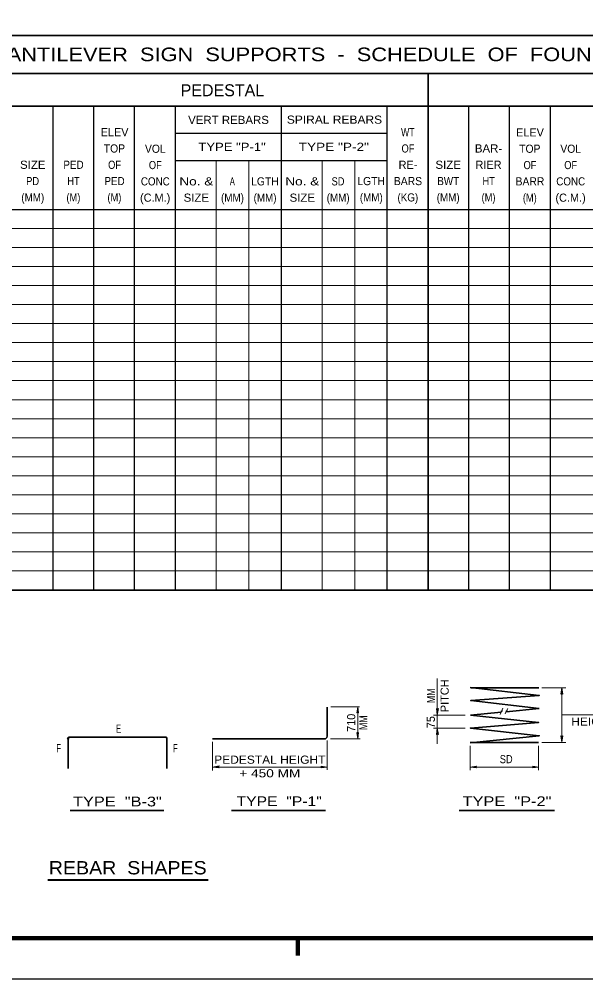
# Model space of a CAD drawing. Extents: x 312601.858 to 312602.699, y 144420.109 to 144420.704.
# Drawn here: x 312602.1757 to 312602.3843, y 144420.1095 to 144420.4624 of the extents above; entities that cross this region are included whole.
import ezdxf
from ezdxf.enums import TextEntityAlignment as Align

# ---------------------------------------------------------------- set-up
doc = ezdxf.new("R2010")
doc.units = 0
doc.header["$LTSCALE"] = 0.0012
doc.header["$PDMODE"] = 32
doc.header["$PDSIZE"] = 0.0006
for name, color, linetype, lineweight in [('1', 7, 'Continuous', 13), ('2', 7, 'Continuous', 13), ('39', 7, 'Continuous', 13)]:
    doc.layers.add(name, color=color, linetype=linetype, lineweight=lineweight)

msp = doc.modelspace()

# ---------------------------------------------------------------- hatches: boundary and pattern name
at = {"layer": '39'}
for points in [[(312602.3754, 144420.2144), (312602.3751, 144420.2142), (312602.3754, 144420.2166), (312602.3758, 144420.2142)], [(312602.3754, 144420.2144), (312602.3751, 144420.2142), (312602.3754, 144420.2166), (312602.3758, 144420.2142)], [(312602.3754, 144420.2144), (312602.3751, 144420.2142), (312602.3754, 144420.2166), (312602.3758, 144420.2142)], [(312602.3296, 144420.2087), (312602.33, 144420.2089), (312602.3296, 144420.2065), (312602.3293, 144420.2089)], [(312602.3296, 144420.1995), (312602.3293, 144420.1993), (312602.3296, 144420.2017), (312602.33, 144420.1993)], [(312602.3754, 144420.1987), (312602.3758, 144420.1989), (312602.3754, 144420.1965), (312602.3751, 144420.1989)], [(312602.3754, 144420.1987), (312602.3758, 144420.1989), (312602.3754, 144420.1965), (312602.3751, 144420.1989)], [(312602.3754, 144420.1987), (312602.3758, 144420.1989), (312602.3754, 144420.1965), (312602.3751, 144420.1989)], [(312602.2491, 144420.1874), (312602.2493, 144420.1871), (312602.2469, 144420.1874), (312602.2493, 144420.1878)], [(312602.2491, 144420.1874), (312602.2493, 144420.1871), (312602.2469, 144420.1874), (312602.2493, 144420.1878)], [(312602.2491, 144420.1874), (312602.2493, 144420.1871), (312602.2469, 144420.1874), (312602.2493, 144420.1878)]]:
    msp.add_hatch(color=256, dxfattribs=at).paths.add_polyline_path(points)

# ---------------------------------------------------------------- linework, layer by layer
at = {"layer": '1', "lineweight": 35}
for p, q in [((312602.159, 144420.4565), (312602.6412, 144420.4565)), ((312602.159, 144420.4425), (312602.6412, 144420.4425)), ((312602.3262, 144420.2525), (312602.3262, 144420.4425)), ((312602.1584, 144420.4305), (312602.6008, 144420.4305)), ((312602.1584, 144420.2525), (312602.6412, 144420.2525)), ((312602.3421, 144420.2165), (312602.367, 144420.2165)), ((312602.289, 144420.2094), (312602.289, 144420.1987)), ((312602.3418, 144420.2065), (312602.3531, 144420.2076)), ((312602.355, 144420.2077), (312602.3671, 144420.2089)), ((312602.1937, 144420.1869), (312602.1937, 144420.198)), ((312602.1941, 144420.1984), (312602.2297, 144420.1984)), ((312602.2301, 144420.198), (312602.2301, 144420.1868)), ((312602.2468, 144420.1977), (312602.288, 144420.1977)), ((312602.3417, 144420.1964), (312602.3669, 144420.1964)), ((312602.1945, 144420.1714), (312602.2289, 144420.1714)), ((312602.2539, 144420.1714), (312602.2885, 144420.1714)), ((312602.3377, 144420.1714), (312602.3727, 144420.1714))]:
    msp.add_line(p, q, dxfattribs=at)
at = {"layer": '1', "lineweight": 25}
for p, q in [((312602.1882, 144420.2525), (312602.1882, 144420.4305)), ((312602.2032, 144420.2525), (312602.2032, 144420.4305)), ((312602.2182, 144420.2525), (312602.2182, 144420.4305)), ((312602.2332, 144420.2525), (312602.2332, 144420.4305)), ((312602.2722, 144420.2525), (312602.2722, 144420.4305)), ((312602.3112, 144420.2525), (312602.3112, 144420.4305)), ((312602.3412, 144420.2525), (312602.3412, 144420.4305)), ((312602.3562, 144420.2525), (312602.3562, 144420.4305)), ((312602.3712, 144420.2525), (312602.3712, 144420.4305)), ((312602.2332, 144420.4205), (312602.3112, 144420.4205)), ((312602.2332, 144420.4105), (312602.3112, 144420.4105)), ((312602.1584, 144420.3925), (312602.6412, 144420.3925))]:
    msp.add_line(p, q, dxfattribs=at)
at = {"layer": '1'}
for p, q in [((312602.2482, 144420.2525), (312602.2482, 144420.4104)), ((312602.2602, 144420.2525), (312602.2602, 144420.4105)), ((312602.2872, 144420.2525), (312602.2872, 144420.4104)), ((312602.2992, 144420.2525), (312602.2992, 144420.4104)), ((312602.1584, 144420.3855), (312602.6412, 144420.3855)), ((312602.1584, 144420.3785), (312602.6412, 144420.3785)), ((312602.1584, 144420.3715), (312602.6412, 144420.3715)), ((312602.1584, 144420.3645), (312602.6412, 144420.3645)), ((312602.1584, 144420.3575), (312602.6412, 144420.3575)), ((312602.1584, 144420.3505), (312602.6412, 144420.3505)), ((312602.1584, 144420.3435), (312602.6412, 144420.3435)), ((312602.1584, 144420.3365), (312602.6412, 144420.3365)), ((312602.1584, 144420.3295), (312602.6412, 144420.3295)), ((312602.1584, 144420.3225), (312602.6412, 144420.3225)), ((312602.1584, 144420.3155), (312602.6412, 144420.3155)), ((312601.9375, 144420.3085), (312602.6412, 144420.3085)), ((312602.1584, 144420.3015), (312602.6412, 144420.3015)), ((312602.1584, 144420.2945), (312602.6412, 144420.2945)), ((312602.1584, 144420.2875), (312602.6412, 144420.2875)), ((312602.1584, 144420.2805), (312602.6412, 144420.2805)), ((312602.1584, 144420.2735), (312602.6412, 144420.2735)), ((312602.1584, 144420.2665), (312602.6412, 144420.2665)), ((312602.1584, 144420.2595), (312602.6412, 144420.2595)), ((312602.3681, 144420.2165), (312602.3769, 144420.2165)), ((312602.3754, 144420.1965), (312602.3754, 144420.2166)), ((312602.2904, 144420.2095), (312602.301, 144420.2095)), ((312602.3003, 144420.1978), (312602.3003, 144420.2095)), ((312602.353, 144420.2079), (312602.3536, 144420.2081)), ((312602.3548, 144420.2079), (312602.3554, 144420.2081)), ((312602.3282, 144420.2065), (312602.3398, 144420.2065)), ((312602.3754, 144420.2066), (312602.4113, 144420.2066)), ((312602.3282, 144420.2017), (312602.3398, 144420.2017)), ((312602.2469, 144420.1967), (312602.2469, 144420.1861)), ((312602.289, 144420.1971), (312602.289, 144420.1864)), ((312602.2903, 144420.1977), (312602.3012, 144420.1977)), ((312602.3681, 144420.1964), (312602.3769, 144420.1964)), ((312602.3417, 144420.1862), (312602.3417, 144420.1952)), ((312602.3669, 144420.1925), (312602.3669, 144420.1952)), ((312602.3669, 144420.1862), (312602.3669, 144420.1942)), ((312602.2469, 144420.1874), (312602.289, 144420.1874)), ((312602.3417, 144420.1874), (312602.3669, 144420.1874))]:
    msp.add_line(p, q, dxfattribs=at)
at = {"layer": '1', "lineweight": 40}
msp.add_line((312602.1862, 144420.1459), (312602.2452, 144420.1459), dxfattribs=at)
at = {"layer": '1', "lineweight": 158}
msp.add_line((312602.2783, 144420.1181), (312602.2783, 144420.1245), dxfattribs=at)
at = {"layer": '1'}
for points in [[(312602.3296, 144420.1959), (312602.3296, 144420.2017), (312602.3296, 144420.2065), (312602.3296, 144420.2199)], [(312602.3527, 144420.2067), (312602.3532, 144420.2078), (312602.3537, 144420.209)], [(312602.353, 144420.2079), (312602.3532, 144420.2078), (312602.3536, 144420.2081)], [(312602.3546, 144420.2069), (312602.355, 144420.2078), (312602.3555, 144420.2089)], [(312602.3548, 144420.2079), (312602.355, 144420.2078), (312602.3554, 144420.2081)]]:
    msp.add_lwpolyline(points, dxfattribs=at)
at = {"layer": '1', "lineweight": 35}
for points in [[(312602.3671, 144420.2089), (312602.3419, 144420.2118), (312602.3671, 144420.2137), (312602.3417, 144420.2166)], [(312602.3417, 144420.1963), (312602.3671, 144420.1989), (312602.3418, 144420.2017), (312602.3669, 144420.2038), (312602.3418, 144420.2065)]]:
    msp.add_lwpolyline(points, dxfattribs=at)
at = {"layer": '1'}
for points in [[(312602.3, 144420.2073), (312602.3003, 144420.2095), (312602.3006, 144420.2073), (312602.3003, 144420.2075)], [(312602.3, 144420.2073), (312602.3003, 144420.2095), (312602.3006, 144420.2073), (312602.3003, 144420.2075)], [(312602.3006, 144420.2001), (312602.3003, 144420.1978), (312602.3, 144420.2001), (312602.3003, 144420.1998)], [(312602.2868, 144420.1877), (312602.289, 144420.1874), (312602.2868, 144420.1871), (312602.287, 144420.1874)], [(312602.344, 144420.1871), (312602.3417, 144420.1874), (312602.344, 144420.1877), (312602.3437, 144420.1874)], [(312602.344, 144420.1871), (312602.3417, 144420.1874), (312602.344, 144420.1877), (312602.3437, 144420.1874)], [(312602.344, 144420.1871), (312602.3417, 144420.1874), (312602.344, 144420.1877), (312602.3437, 144420.1874)], [(312602.3647, 144420.1877), (312602.3669, 144420.1874), (312602.3647, 144420.1871), (312602.3649, 144420.1874)], [(312602.3647, 144420.1877), (312602.3669, 144420.1874), (312602.3647, 144420.1871), (312602.3649, 144420.1874)]]:
    msp.add_lwpolyline(points, close=True, dxfattribs=at)
at = {"layer": '1', "lineweight": 35}
for centre, radius, start, end in [((312602.1942, 144420.1979), 0.0005, 96.30365, 175.33433), ((312602.2296, 144420.1979), 0.0005, 4.66567, 83.69635), ((312602.288, 144420.1987), 0.001, 270, 0)]:
    msp.add_arc(centre, radius, start, end, dxfattribs=at)
at = {"layer": '1'}
msp.add_point((312602.1937, 144420.1979), dxfattribs=at)
at = {"layer": '39', "lineweight": 158}
msp.add_line((312602.2783, 144420.1181), (312602.2783, 144420.1245), dxfattribs=at)
at = {"layer": '39', "lineweight": 25}
msp.add_lwpolyline([(312601.8578, 144420.1095), (312602.6988, 144420.1095), (312602.6988, 144420.7035)], dxfattribs=at)
at = {"layer": '39', "lineweight": 158}
msp.add_lwpolyline([(312601.9088, 144420.1245), (312602.6838, 144420.1245), (312602.6838, 144420.6645)], dxfattribs=at)
at = {"layer": '39'}
for points in [[(312602.3754, 144420.2144), (312602.3751, 144420.2142), (312602.3754, 144420.2166), (312602.3758, 144420.2142)], [(312602.3754, 144420.2144), (312602.3751, 144420.2142), (312602.3754, 144420.2166), (312602.3758, 144420.2142)], [(312602.3754, 144420.2144), (312602.3751, 144420.2142), (312602.3754, 144420.2166), (312602.3758, 144420.2142)], [(312602.3296, 144420.2087), (312602.33, 144420.2089), (312602.3296, 144420.2065), (312602.3293, 144420.2089)], [(312602.3296, 144420.1995), (312602.3293, 144420.1993), (312602.3296, 144420.2017), (312602.33, 144420.1993)], [(312602.3754, 144420.1987), (312602.3758, 144420.1989), (312602.3754, 144420.1965), (312602.3751, 144420.1989)], [(312602.3754, 144420.1987), (312602.3758, 144420.1989), (312602.3754, 144420.1965), (312602.3751, 144420.1989)], [(312602.3754, 144420.1987), (312602.3758, 144420.1989), (312602.3754, 144420.1965), (312602.3751, 144420.1989)], [(312602.2491, 144420.1874), (312602.2493, 144420.1871), (312602.2469, 144420.1874), (312602.2493, 144420.1878)], [(312602.2491, 144420.1874), (312602.2493, 144420.1871), (312602.2469, 144420.1874), (312602.2493, 144420.1878)], [(312602.2491, 144420.1874), (312602.2493, 144420.1871), (312602.2469, 144420.1874), (312602.2493, 144420.1878)]]:
    msp.add_lwpolyline(points, close=True, dxfattribs=at)

# ---------------------------------------------------------------- texts
at = {"layer": '1'}
for s, p in [('PITCH', (312602.3338, 144420.2136)), ('75', (312602.3287, 144420.2039))]:
    msp.add_text(s, height=0.003, rotation=90, dxfattribs=at).set_placement(p, align=Align.CENTER)
at = {"layer": '1', "width": 0.8}
msp.add_text('MM', height=0.003, rotation=90, dxfattribs=at).set_placement((312602.3288, 144420.2136), align=Align.CENTER)
at = {"layer": '1'}
for s, width, p in [('HEIGHT-50 MM', 1.1, (312602.3947, 144420.2026)), ('PEDESTAL HEIGHT', 1.1, (312602.26795, 144420.1886)), ('+ 450 MM', 1.25, (312602.26795, 144420.1836))]:
    msp.add_text(s, height=0.003, dxfattribs=dict(at, width=width)).set_placement(p, align=Align.CENTER)
at = {"layer": '2'}
for s, height, width, p in [('CANTILEVER  SIGN  SUPPORTS  -  SCHEDULE  OF  FOUNDATIONS', 0.005, 1.2, (312602.2937, 144420.447)), ('VERT REBARS', 0.003, 1.05, (312602.25275, 144420.4239)), ('SPIRAL REBARS', 0.003, 1.1, (312602.29175, 144420.424)), ('WT', 0.003, 0.8, (312602.31875, 144420.4194)), ('TOP', 0.003, 0.95, (312602.21075, 144420.4134)), ('VOL', 0.003, 0.95, (312602.2258, 144420.4133)), ('TYPE "P-1"', 0.003, 1.2, (312602.25405, 144420.414)), ('TYPE "P-2"', 0.003, 1.25, (312602.2915, 144420.414)), ('OF', 0.003, 0.85, (312602.3188, 144420.4134)), ('BAR-', 0.003, 1.05, (312602.34845, 144420.4134)), ('TOP', 0.003, 0.95, (312602.36365, 144420.4133)), ('VOL', 0.003, 0.95, (312602.3787, 144420.4133)), ('SIZE', 0.003, 1.05, (312602.1807, 144420.4074)), ('PED', 0.003, 0.9, (312602.1957, 144420.4074)), ('OF', 0.003, 0.85, (312602.2108, 144420.4074)), ('OF', 0.003, 0.85, (312602.2258, 144420.4073)), ('SIZE', 0.003, 1.05, (312602.3336, 144420.4074)), ('OF', 0.003, 0.85, (312602.3637, 144420.4073)), ('OF', 0.003, 0.85, (312602.3787, 144420.4073)), ('PD', 0.003, 0.85, (312602.18065, 144420.4014)), ('HT', 0.003, 0.85, (312602.1957, 144420.4014)), ('PED', 0.003, 0.9, (312602.2108, 144420.4014)), ('CONC', 0.003, 0.9, (312602.2258, 144420.4013)), ('No. &', 0.003, 1.25, (312602.2409, 144420.4013)), ('A', 0.003, 0.7, (312602.25415, 144420.4013)), ('LGTH', 0.003, 0.95, (312602.26615, 144420.4013)), ('No. &', 0.003, 1.25, (312602.2799, 144420.4013)), ('SD', 0.003, 0.85, (312602.29305, 144420.4013)), ('LGTH', 0.003, 0.95, (312602.30525, 144420.4014)), ('BARS', 0.003, 0.95, (312602.3188, 144420.4014)), ('BWT', 0.003, 0.9, (312602.3336, 144420.4014)), ('HT', 0.003, 0.85, (312602.3485, 144420.4014)), ('BARR', 0.003, 0.95, (312602.3637, 144420.4013)), ('CONC', 0.003, 0.9, (312602.3787, 144420.4013)), ('(MM)', 0.003, 0.9, (312602.1807, 144420.3954)), ('(M)', 0.003, 0.85, (312602.19565, 144420.3954)), ('(M)', 0.003, 0.85, (312602.21075, 144420.3954)), ('SIZE', 0.003, 1.05, (312602.2409, 144420.3953)), ('(MM)', 0.003, 0.9, (312602.2542, 144420.3953)), ('(MM)', 0.003, 0.9, (312602.2662, 144420.3953)), ('SIZE', 0.003, 1.05, (312602.2799, 144420.3953)), ('(MM)', 0.003, 0.9, (312602.2931, 144420.3953)), ('(MM)', 0.003, 0.9, (312602.3053, 144420.3954)), ('(KG)', 0.003, 0.9, (312602.31875, 144420.3954)), ('(MM)', 0.003, 0.9, (312602.3336, 144420.3954)), ('(M)', 0.003, 0.85, (312602.34845, 144420.3954)), ('(M)', 0.003, 0.85, (312602.36365, 144420.3953)), ('E', 0.003, 0.7, (312602.2123, 144420.2)), ('F', 0.003, 0.7, (312602.19025, 144420.1928)), ('F', 0.003, 0.7, (312602.23315, 144420.1928)), ('SD', 0.003, 0.85, (312602.35495, 144420.1888)), ('TYPE  "B-3"', 0.0036, 1.25, (312602.21185, 144420.1729)), ('TYPE  "P-1"', 0.0036, 1.2, (312602.2714, 144420.173)), ('TYPE  "P-2"', 0.0036, 1.25, (312602.35525, 144420.173)), ('REBAR  SHAPES', 0.0049, 1.1, (312602.21565, 144420.1479))]:
    msp.add_text(s, height=height, dxfattribs=dict(at, width=width)).set_placement(p, align=Align.CENTER)
for s, height, p in [('PEDESTAL', 0.0044, (312602.2505, 144420.4341)), ('ELEV', 0.003, (312602.2108, 144420.4194)), ('ELEV', 0.003, (312602.3637, 144420.4193)), ('RE-', 0.003, (312602.3188, 144420.4074)), ('RIER', 0.003, (312602.34845, 144420.4074)), ('(C.M.)', 0.003, (312602.22575, 144420.3953)), ('(C.M.)', 0.003, (312602.37865, 144420.3953))]:
    msp.add_text(s, height=height, dxfattribs=at).set_placement(p, align=Align.CENTER)
msp.add_text('710', height=0.003, rotation=90, dxfattribs=at).set_placement((312602.2994, 144420.20365), align=Align.CENTER)
at = {"layer": '2', "width": 0.8}
msp.add_text('MM', height=0.003, rotation=90, dxfattribs=at).set_placement((312602.3039, 144420.2037), align=Align.CENTER)

doc.saveas('drawing.dxf')
